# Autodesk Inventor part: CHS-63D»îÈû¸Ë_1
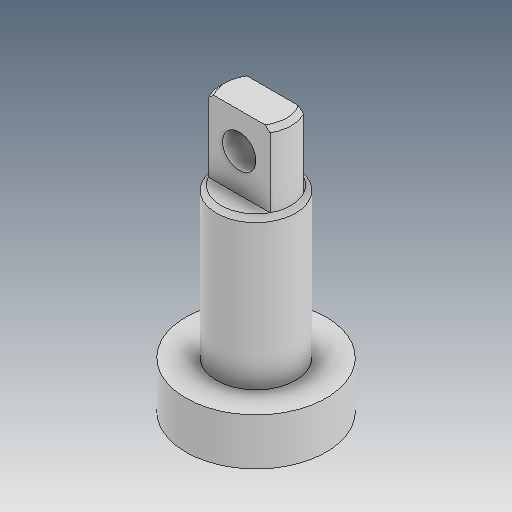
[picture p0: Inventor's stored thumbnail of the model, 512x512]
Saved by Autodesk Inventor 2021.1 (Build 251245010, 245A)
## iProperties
Created: 2019-05
Part Number: CHS-63D»îÈû¸Ë_1
Material: Ogólny
Document SubType Name: Modeling
Designer: user
Density: 1 g/cm^3
Appearance: Domyślna
Author: user
Revision Number: ÈÎºÎ
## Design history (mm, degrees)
feature "ÊäÈë1"
feature "ÊäÈë2"
node "Bryła1"
node "Bryła2"
